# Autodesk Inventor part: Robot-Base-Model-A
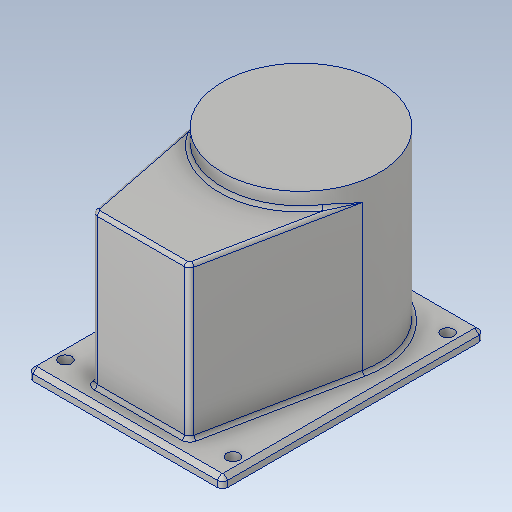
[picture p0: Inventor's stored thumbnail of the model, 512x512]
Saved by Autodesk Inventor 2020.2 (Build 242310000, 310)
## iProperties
Created: 2018-07
Part Number: Robot-Base-Model-A
Material: Aluminum 6061
Description: 123456
Document SubType Name: Modeling
Designer: Power User
Mass: 12717.4 g
Surface Area: 1979.97 cm^2
Volume: 4710.14 cm^3
Density: 2.7 g/cm^3
Appearance: Aluminum - Flat
Title: GEAR
Author: Power User
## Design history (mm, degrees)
sketch "Sketch6"
  geometry: L1 (93, 125)-(-93, 125); L2 (-93, 125)-(-93, -125); L3 (-93, -125)-(93, -125); L4 (93, -125)-(93, 125); L5 (93, 125)-(-93, -125); L6 (-93, 125)-(93, -125); 1 further point
  constraints: 12 end point, 2 midpoint, 2 parallel, 1 horizontal, 1 perpendicular
  dimensions: "d44" = 250 distance of L3.end L1.start; "d45" = 186 distance of L2.end L3.end
extrude "Extrusion5" new body sketch "Sketch6" distance "d46" = 10; taper "d47" = 0 deg
fillet "Fillet6" dims "d78" = 5
chamfer "Chamfer3" distance "d79" = 4; stored, may be unused: second distance "d80" = 2, angle "d81" = 135 deg
sketch "Sketch7"
  geometry: L1 (-93, -125)-(93, -125) reference; L2 (-73.533, 28.237)-(-45.78, -110); L3 (-45.78, -110)-(45.78, -110); L4 (45.78, -110)-(73.533, 28.237); A1 r 75 centre (0, 43) between (-73.533, 28.237) and (73.533, 28.237); 2 further points
  constraints: 6 end point, 2 point on circle, 2 tangent, 2 vertical alignment, 1 centre point, 1 horizontal, 1 midpoint
  dimensions: "d48" = 150 diameter of A1; "d49" = 168 distance from line of A1.centre L1; "d50" = 91.56 distance of L2.end L3.end; "d51" = 15 distance between parallel lines of L3 L1
extrude "Extrusion6" join sketch "Sketch7" distance "d52" = 160; taper "d53" = 0 deg
extrude "Extrusion7" join sketch "Sketch7" distance "d54" = 145; taper "d55" = 0 deg
sketch "Sketch8"
  geometry: L1 (-93, 125)-(-93, -125) reference; L2 (93, 125)-(-93, 125) reference; 2 further points
  dimensions: "d56" = 13 distance from line of L1 point (-80, 103); "d57" = 22 distance from line of L2 point (-80, 103)
hole "Hole2" sketch "Sketch8" at (-80, 103) diameter "d58" = 12; stored, may be unused: countersink angle "d62" = 90 deg, drill point angle "d64" = 118 deg; dims "d59" = 6, "d60" = 25, "d61" = 10, "d63" = 8
pattern_linear "Rectangular Pattern1" dims "d67" = 205, "d70" = 160
fillet "Fillet2" dims "d74" = 5
fillet "Fillet3" dims "d75" = 3
body "Solid2"
